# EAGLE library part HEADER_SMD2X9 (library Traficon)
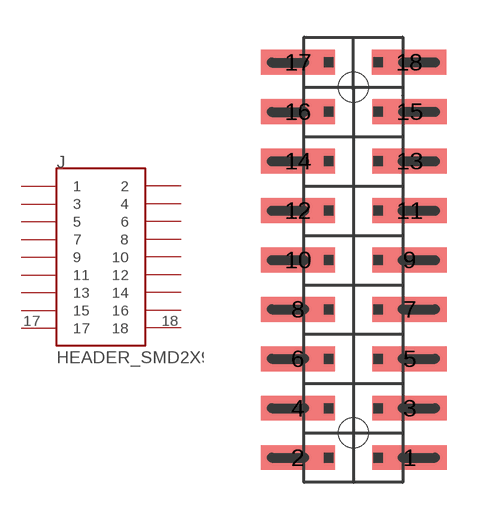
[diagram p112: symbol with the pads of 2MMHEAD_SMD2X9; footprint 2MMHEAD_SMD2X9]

Designator prefix J

## HEADER_SMD2X9  [2MMHEAD_SMD2X9]
1  1  pas
2  2  pas
3  3  pas
4  4  pas
5  5  pas
6  6  pas
7  7  pas
8  8  pas
9  9  pas
10  10  pas
11  11  pas
12  12  pas
13  13  pas
14  14  pas
15  15  pas
16  16  pas
17  17  pas
18  18  pas

## Footprint 2MMHEAD_SMD2X9 (pad centres in mm)
smd 3 x 1: 1 2.275,-8.006; 2 -2.245,-8.006; 3 2.275,-6.006; 4 -2.245,-6.006; 5 2.275,-4.006; 6 -2.245,-4.006; 7 2.275,-2.006; 8 -2.245,-2.006; 9 2.275,-0.006; 10 -2.245,-0.006; 11 2.275,1.994; 12 -2.245,1.994; 13 2.275,3.994; 14 -2.245,3.994; 15 2.275,5.994; 16 -2.245,5.994; 17 -2.245,7.994; 18 2.255,7.994
hole 1.2 at 0.003,6.991
hole 1.2 at 0,-6.995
